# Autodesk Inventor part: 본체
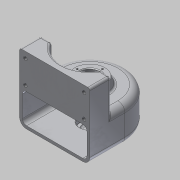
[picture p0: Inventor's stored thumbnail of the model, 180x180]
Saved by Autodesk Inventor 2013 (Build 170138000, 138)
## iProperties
Created: 2015-02
Part Number: 본체
Material: 알루미늄 6061
Document SubType Name: Modeling
Designer: Administrator
Density: 2.71 g/cm^3
Mass: 575.526 g
Surface Area: 706.56 cm^2
Volume: 212.371 cm^3
Author: Administrator
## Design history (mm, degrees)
sketch "스케치1"
  geometry: L1 (-50, -50)-(50, -50); L2 (50, -50)-(50, 0); L3 (-50, -50)-(-50, 0); A1 r 50 centre (0, 0) between (50, 0) and (-50, 0); 2 further points
  constraints: 6 end point, 2 midpoint, 2 point on circle, 2 tangent, 2 vertical, 1 centre point, 1 coincident, 1 horizontal, 1 vertical alignment
  dimensions: "d0" = 100 diameter of A1; "d1" = 50 distance from line of point (0, 0) L1
extrude "돌출1" new body sketch "스케치1" stored distance "d2" = 50; taper "d3" = 0 deg
sketch "스케치2"
  geometry: L1 (50, -50)-(-50, -50) reference; L2 (-50, -50)-(-50, 0) reference; L3 (50, 0)-(50, -50) reference; L4 (-46, 0)-(-46, -50); L5 (46, 0)-(46, -50); A1 r 50 centre (0, 0) between (50, 0) and (-50, 0) reference; A2 r 46 centre (0, 0) between (46, 0) and (-46, 0); 1 further point
  constraints: 4 end point, 2 perpendicular, 2 point on circle, 2 point on line, 2 tangent, 1 centre point, 1 coincident
  dimensions: "d4" = 92 diameter of A2
extrude "돌출2" cut sketch "스케치2" stored distance "d5" = 42; taper "d6" = 0 deg
sketch "스케치3"
  geometry: L1 (-50, -50)-(50, -50) reference; L2 (-50, -50)-(50, -50) reference; L3 (50, -50)-(50, 0) reference; L4 (-50, 0)-(-50, -50) reference; L5 (-50, -50)-(50, -50); L6 (50, -50)-(50, -20); L7 (50, -20)-(34.641, -20); L8 (-50, -50)-(-50, -20); L9 (-50, -20)-(-34.641, -20); A1 r 50 centre (0, 0) between (50, 0) and (-50, 0) reference; A2 r 40 centre (0, 0) between (-34.641, -20) and (34.641, -20)
  constraints: 10 end point, 2 collinear, 2 perpendicular, 2 point on circle, 2 point on line, 1 centre point, 1 coincident
  dimensions: "d7" = 80 diameter of A2; "d8" = 30 distance between parallel lines of L1 L7
extrude "돌출3" join sketch "스케치3" distance "d9" = 45; taper "d10" = 0 deg
sketch "스케치4"
  geometry: C1 r 25 at (0, 0); A1 r 40 centre (0, 0) between (-34.641, -20) and (34.641, -20) reference
  constraints: 1 centre point, 1 coincident
  dimensions: "d11" = 50 diameter of C1
extrude "돌출4" join sketch "스케치4" distance "d12" = 10; taper "d13" = 0 deg
hole "구멍1" diameter "d16" = 20; stored, may be unused: countersink angle "d20" = 90 deg, drill point angle "d22" = 118 deg; dims "d14" = 10, "d15" = 10, "d17" = 6, "d18" = 28, "d19" = 10, "d21" = 28.75
feature "면 기울기1" dims angle "d23" = 20 deg
sketch "스케치5"
  geometry: C1 r 20 at (0, 0); A1 r 50 centre (0, 0) between (50, 0) and (-50, 0) reference
  constraints: 1 centre point, 1 coincident
  dimensions: "d24" = 40 diameter of C1
extrude "돌출5" join sketch "스케치5" distance "d26" = 9; taper "d27" = 0 deg
hole "구멍2" diameter "d30" = 20; stored, may be unused: countersink angle "d34" = 90 deg, drill point angle "d36" = 0 deg; dims "d28" = 10, "d29" = 10, "d31" = 6, "d32" = 28, "d33" = 8, "d35" = 10
sketch "스케치6"
  geometry: C1 r 14 at (0, 0) reference; 1 further point
  constraints: 1 vertical alignment
  dimensions: "d37" = 18 distance of point (0, 18) C1.centre
hole "구멍3" sketch "스케치6" at (0, 18) diameter "d38" = 2.459; stored, may be unused: countersink angle "d42" = 90 deg, drill point angle "d44" = 118 deg; dims "d39" = 6, "d40" = 28, "d41" = 8, "d43" = 9
sketch "스케치7"
  geometry: L1 (100, 0)-(100, 95) reference; L2 (0, 95)-(100, 95) reference; 5 further points
  constraints: 2 horizontal alignment, 2 vertical alignment
  dimensions: "d49" = 9 distance from line of L2 point (91.75, 86); "d50" = 33 distance of point (91.75, 53) point (91.75, 86); "d51" = 83.5 distance of point (8.25, 86) point (91.75, 86); "d52" = 8.25 distance from line of point (91.75, 86) L1
hole "구멍4" sketch "스케치7" at (91.75, 86), (91.75, 53), (8.25, 86), (8.25, 53) diameter "d53" = 5.134; stored, may be unused: countersink angle "d57" = 90 deg, drill point angle "d59" = 118 deg; dims "d54" = 10, "d55" = 28, "d56" = 8, "d58" = 13
fillet "모깎기1" dims "d60" = 6, "d61" = 10
fillet "모깎기2" dims "d62" = 0.3
fillet "모깎기3" dims "d63" = 3
fillet "모깎기4" dims "d64" = 3
chamfer "모따기1" distance "d65" = 1; stored, may be unused: second distance "d66" = 2, angle "d67" = 45 deg
node "작업 평면1"
sketch "스케치8"
  geometry: L1 (40, -25)-(-40, -25) reference; 2 further points
  constraints: 1 coincident, 1 other
  dimensions: "d68" = 25 distance from line of point (0, 0) L1
feature "엠보싱1" sketch "스케치8" dims "d0" = 100, "d1" = 50, "d69" = 0.5, "d70" = 0
fillet "모깎기5" dims "d71" = 3
node "솔리드1"
pattern_circular "원형 패턴1" dims angle "d46" = 360 deg
node "투영된 루프1"
node "투영된 루프2"
